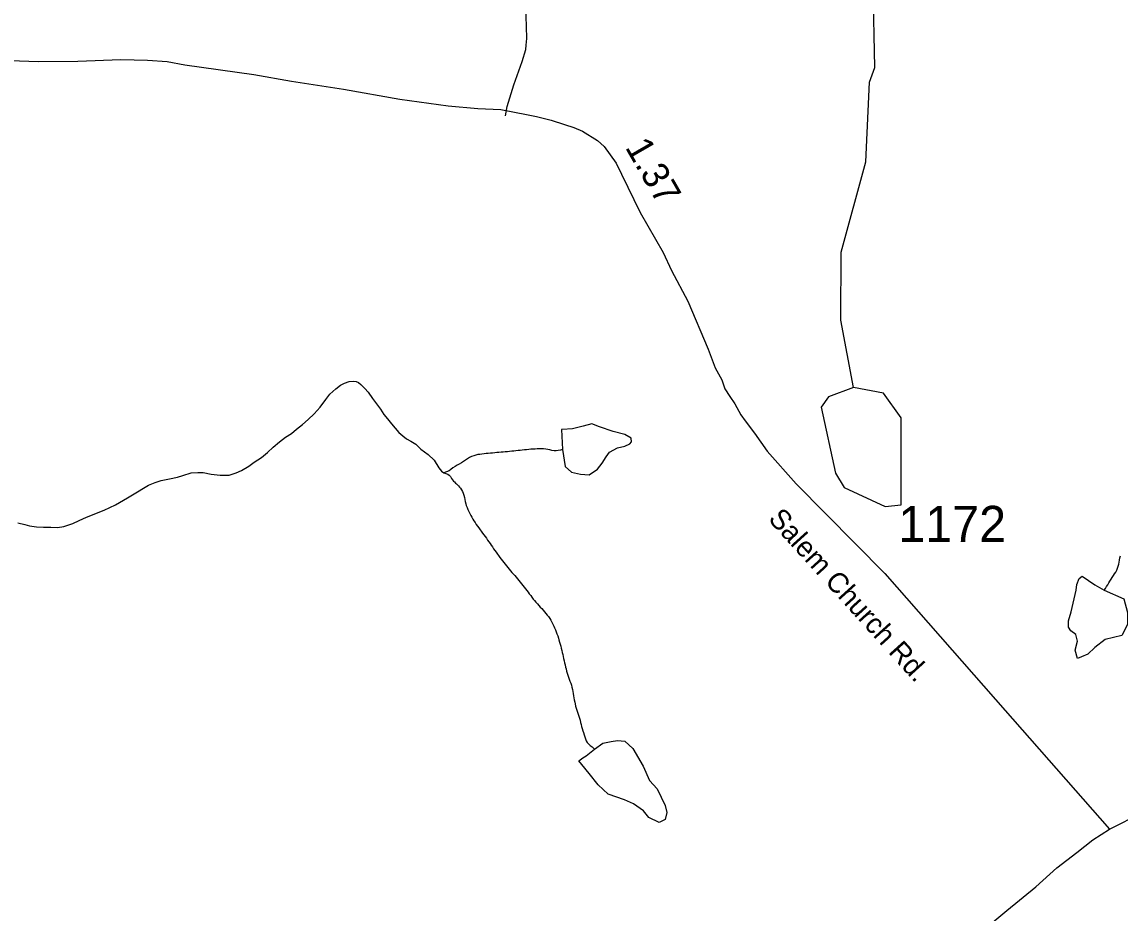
# Model space of a CAD drawing. Extents: x 1950930 to 2061844, y 904556 to 1017002.
# Drawn here: x 1961242 to 1966393, y 925393 to 929573 of the extents above; entities that cross this region are included whole.
import ezdxf

# ---------------------------------------------------------------- set-up
doc = ezdxf.new("R2010")
doc.units = 0
for name, color, linetype in [('Exist Hydrographic Creek Single Shore', 7, 'Continuous'), ('Exist Hydrographic Misc Water Feature', 7, 'Continuous'), ('Exist Road Non-System Type 51', 7, 'Continuous'), ('Exist Road Primary NC Attributed', 7, 'Continuous'), ('Exist Road Primary US Structure Standard Bridge CELL', 7, 'Continuous'), ('Exist Road Secondary Type 51 Attributed', 7, 'Continuous'), ('Exist Road Secondary Type 51 Label', 7, 'Continuous'), ('Exist Road Secondary Type 51 Number Label', 7, 'Continuous')]:
    doc.layers.add(name, color=color, linetype=linetype)

msp = doc.modelspace()

# ---------------------------------------------------------------- linework, layer by layer
at = {"layer": 'Exist Hydrographic Creek Single Shore'}
for points in [[(1965142.6, 927858.2), (1965083.6, 928174.5), (1965084.6, 928492.9), (1965200.6, 928917.2), (1965217.7, 929290.9), (1965242.7, 929359.4), (1965234.7, 929740.3), (1964918.5, 930383.4), (1964901.7, 930524.9), (1964960.5, 930691.1), (1965293.5, 930917.3), (1965435.6, 931058.8), (1965502.5, 931208.4), (1965403.6, 932175.3), (1965436.6, 932726), (1965461.7, 932758.3), (1965474.2, 932813.4), (1965470.9, 932879.2), (1965457.1, 932929.6)], [(1961222.7, 927223.6), (1961254.7, 927215.5), (1961276.6, 927209.4), (1961310.7, 927205.4), (1961342.7, 927203.3), (1961376.7, 927203.3), (1961408.7, 927201.2), (1961438.8, 927207.2), (1961480.9, 927221), (1961510.8, 927235), (1961544.8, 927251), (1961627.1, 927282.8), (1961681, 927308.7), (1961737.2, 927340.6), (1961783.1, 927368.4), (1961811.2, 927386.4), (1961835.2, 927400.4), (1961867.2, 927412.3), (1961895.3, 927422.3), (1961933.2, 927430.3), (1961971.1, 927438.2), (1961997.2, 927446.2), (1962035.3, 927458), (1962067.3, 927460), (1962091.3, 927459.9), (1962129.4, 927451.9), (1962171.3, 927447.8), (1962213.3, 927447.7), (1962247.3, 927457.6), (1962271.3, 927469.6), (1962305.4, 927489.5), (1962331.4, 927507.5), (1962365.5, 927529.4), (1962393.5, 927553.4), (1962419.6, 927579.3), (1962449.5, 927603.2), (1962477.6, 927625.2), (1962505.7, 927643.2), (1962529.7, 927663.1), (1962557.8, 927685), (1962583.8, 927709), (1962611.9, 927735), (1962640, 927767), (1962667.9, 927802.9), (1962686.2, 927826.8), (1962714, 927852.8), (1962736.2, 927868.8), (1962754.2, 927878.7), (1962776.2, 927886.6), (1962796.3, 927888.7), (1962810.2, 927886.6), (1962820.3, 927882.6), (1962832.2, 927872.6), (1962850.2, 927854.5), (1962866.2, 927836.5), (1962886.1, 927806.4), (1962900, 927788.5), (1962924, 927756.4), (1962940, 927732.3), (1962955.8, 927712.3), (1962975.9, 927688.2), (1962991.9, 927668.2), (1963009.7, 927648.2), (1963027.8, 927632.2), (1963045.8, 927618.1), (1963065.7, 927606.1), (1963089.7, 927592.1), (1963113.7, 927569.9), (1963147.5, 927543.9), (1963175.4, 927517.9), (1963197.6, 927481.8), (1963209.5, 927465.8), (1963221.3, 927457.7)], [(1963221.3, 927457.7), (1963239.4, 927451.8), (1963245.7, 927448), (1963251.5, 927440.3), (1963256.4, 927431.9), (1963261.3, 927425.8), (1963266.3, 927419.8), (1963271.4, 927415.3), (1963276.3, 927410.5), (1963281, 927405.9), (1963285.7, 927401.8), (1963290.4, 927396.7), (1963295, 927391.2), (1963299.5, 927385.6), (1963303.8, 927378.7), (1963308.1, 927370.9), (1963311.8, 927362.8), (1963314.8, 927353.9), (1963317.3, 927343), (1963319.6, 927333.2), (1963321.2, 927323.2), (1963323.7, 927313.4), (1963326.3, 927304.3), (1963330, 927295.2), (1963333.9, 927286.1), (1963338.2, 927277), (1963342.7, 927267.9), (1963347.5, 927258.7), (1963352.2, 927250.4), (1963357.3, 927241.3), (1963362.2, 927233), (1963367.5, 927224.7), (1963373.1, 927216.4), (1963378.8, 927208), (1963384.6, 927199.7), (1963390.7, 927191.4), (1963396.7, 927183.9), (1963402.4, 927175.6), (1963408.6, 927167.2), (1963414.5, 927159.7), (1963420.4, 927151.4), (1963426.2, 927143.1), (1963431.5, 927134.8), (1963437.5, 927126.5), (1963443.2, 927118.9), (1963449, 927110.6), (1963454.5, 927102.3), (1963460.4, 927094), (1963466.4, 927085.7), (1963471.9, 927077.4), (1963477.9, 927069.8), (1963483.6, 927061.5), (1963489.6, 927053.2), (1963495.7, 927045.6), (1963501.9, 927037.3), (1963508.2, 927029.8), (1963514.6, 927022.2), (1963520.9, 927014.7), (1963527.5, 927006.4), (1963533.6, 926998.8), (1963540.2, 926991.4), (1963546.8, 926983.9), (1963553.3, 926976.3), (1963559.7, 926968.8), (1963566, 926961.3), (1963572.6, 926952.9), (1963579, 926945.4), (1963585.1, 926937.9), (1963591.5, 926929.6), (1963597.2, 926922.2), (1963603.6, 926913.7), (1963609.7, 926906.3), (1963615.7, 926898), (1963621.8, 926890.5), (1963628.2, 926882.1), (1963634.1, 926874.6), (1963640.5, 926866.3), (1963646.4, 926858.8), (1963652.8, 926851.2), (1963659.5, 926843.7), (1963666.1, 926836.2), (1963672.9, 926828.6), (1963679.8, 926821.2), (1963686.4, 926813.7), (1963693.6, 926806.1), (1963699.9, 926798.6), (1963706.3, 926791.1), (1963712.4, 926783.5), (1963718, 926775.2), (1963722.9, 926766.9), (1963727.6, 926757.8), (1963732.1, 926748.7), (1963736.4, 926739.6), (1963740.3, 926730.4), (1963744.4, 926721.3), (1963747.9, 926712.3), (1963751.4, 926702.3), (1963754.9, 926693.2), (1963758, 926683.4), (1963761, 926674.2)], [(1966319.3, 926907.8), (1966324.6, 926915.9), (1966330.1, 926924.8), (1966335.5, 926932.9), (1966340.8, 926941.8), (1966345.9, 926949.9), (1966351.5, 926958.9), (1966356.6, 926967), (1966361.9, 926975.9), (1966367.5, 926984), (1966372.8, 926992.9), (1966377.3, 927001), (1966381.2, 927010.7), (1966384.5, 927019.7), (1966386.7, 927029.5), (1966388.6, 927039.3), (1966390.4, 927049.1), (1966392.5, 927058.9), (1966394.7, 927068.7)], [(1963761, 926674.2), (1963764.1, 926664.3), (1963766.8, 926654.5), (1963769.4, 926645.3), (1963771.9, 926635.5), (1963774.2, 926625.5), (1963776.4, 926615.6), (1963778.7, 926606.6), (1963780.9, 926596.7), (1963783, 926586.8), (1963785, 926576.9), (1963787.3, 926567), (1963789.3, 926557.2), (1963791.6, 926547.2), (1963794.1, 926538.2), (1963796.5, 926528.2), (1963799.2, 926518.4), (1963802.3, 926509.3), (1963805.5, 926499.3), (1963809.2, 926490.2), (1963812.7, 926480.4), (1963816.2, 926471.2), (1963819.1, 926462.2), (1963821.5, 926452.3), (1963823.8, 926442.3), (1963826, 926432.5), (1963827.7, 926422.6), (1963829.5, 926412.7), (1963831.2, 926402.9), (1963833, 926392.9), (1963834.7, 926383.1), (1963836.9, 926374), (1963839.2, 926364.1), (1963841.6, 926354.3), (1963844.7, 926345.1), (1963847.8, 926335.3), (1963851.5, 926326.2), (1963854.5, 926316.2), (1963857.4, 926307.1), (1963860.1, 926297.3), (1963862.3, 926287.3), (1963864.8, 926277.5), (1963867.3, 926268.3), (1963869.9, 926258.4), (1963872.8, 926248.6), (1963875.7, 926239.5), (1963878.5, 926229.6), (1963881.6, 926219.6), (1963885.1, 926210.5), (1963889.2, 926201.4), (1963893.9, 926193.1), (1963900.5, 926185.6), (1963907.9, 926178.9), (1963916.1, 926172.2), (1963928, 926162)]]:
    msp.add_lwpolyline(points, dxfattribs=at)
at = {"layer": 'Exist Hydrographic Misc Water Feature'}
for points in [[(1965142.6, 927858.2), (1965025.5, 927814.8), (1964991.5, 927766.2), (1965058.5, 927456.3), (1965099.6, 927389.8), (1965291.7, 927300.6), (1965366.5, 927308.8), (1965366.5, 927715.7), (1965283.7, 927832.4), (1965142.6, 927858.2)], [(1963777.4, 927567.5), (1963790.2, 927487.6), (1963820.1, 927461.4), (1963862.1, 927451.6), (1963902.3, 927448.3), (1963942.1, 927476.2), (1963963.8, 927502.9), (1963981.7, 927532.9), (1963997.5, 927554.6), (1964035.2, 927575.2), (1964069.2, 927583.5), (1964093, 927593.7), (1964101, 927603.4), (1964099, 927621.5), (1964070.7, 927637.7), (1964014.7, 927652.8), (1963950.5, 927674.6), (1963914.4, 927688.4), (1963874.4, 927677.8), (1963824.8, 927664), (1963776.6, 927661), (1963772.5, 927661.1), (1963777.4, 927567.5)], [(1963777.4, 927567.5), (1963767.4, 927565.2), (1963757.8, 927562.8), (1963747.9, 927561.4), (1963738.1, 927561.7), (1963728.2, 927563.5), (1963718.2, 927566.1), (1963708.5, 927568), (1963698.7, 927569.8), (1963688.9, 927570.8), (1963678.8, 927571.1), (1963668.8, 927571.2), (1963658.7, 927570.6), (1963648.9, 927570), (1963638.8, 927569.4), (1963628.8, 927568.9), (1963618.9, 927568.3), (1963609.1, 927566.7), (1963598.8, 927566.1), (1963589, 927564.7), (1963579, 927563.2), (1963569.1, 927562.6), (1963559.3, 927561.2), (1963549.4, 927559.8), (1963539.2, 927559.1), (1963529.3, 927558.5), (1963519.3, 927557.2), (1963509.2, 927556.5), (1963499.4, 927555.9), (1963489.6, 927555.3), (1963479.5, 927553.8), (1963469.5, 927553.2), (1963459.4, 927552.6), (1963449.6, 927551.2), (1963439.5, 927550.6), (1963429.5, 927549.2), (1963419.8, 927548.5), (1963409.8, 927547.9), (1963399.7, 927546.4), (1963389.9, 927545), (1963380.1, 927543.6), (1963370.4, 927541.3), (1963360.8, 927538.2), (1963351.3, 927535.2), (1963341.7, 927530.2), (1963332.3, 927523.7), (1963322.8, 927517.3), (1963313.2, 927511), (1963303.2, 927505.2), (1963293.3, 927499.5), (1963283.1, 927493.8), (1963273.4, 927487.6), (1963263.6, 927481.6), (1963254.4, 927474.4), (1963245.3, 927468.3), (1963221.3, 927457.7)], [(1966319.3, 926907.8), (1966411.5, 926866.6), (1966428.2, 926803), (1966428.6, 926746.4), (1966400.9, 926694.4), (1966323.2, 926675.6), (1966275.4, 926639.6), (1966241.8, 926607.5), (1966211.8, 926595), (1966193.8, 926587.1), (1966183.3, 926626.8), (1966193.2, 926669.2), (1966185, 926700.6), (1966162.8, 926716.6), (1966150.7, 926734.8), (1966150.7, 926764.5), (1966164, 926806.8), (1966173.9, 926846.8), (1966187.4, 926907.3), (1966191.1, 926935.1), (1966201, 926962.8), (1966214.7, 926973.1), (1966275.2, 926933.3), (1966319.3, 926907.8)], [(1963928, 926162), (1963966.1, 926190), (1964005.7, 926198.2), (1964035.8, 926202.5), (1964069.8, 926199.3), (1964108, 926164.9), (1964156.6, 926081.9), (1964185.1, 926015.7), (1964221.6, 925976.4), (1964259.9, 925898.4), (1964266.3, 925864.7), (1964258.5, 925832), (1964230.6, 925817.8), (1964182.4, 925841.8), (1964158.2, 925873.4), (1964110, 925905.6), (1964068, 925924.6), (1963991.7, 925950.7), (1963945.2, 925994.4), (1963902.9, 926047.7), (1963868.7, 926089.5), (1963854.5, 926107), (1963872.4, 926121.3), (1963888.4, 926130), (1963928, 926162)]]:
    msp.add_lwpolyline(points, dxfattribs=at)
at = {"layer": 'Exist Road Non-System Type 51'}
msp.add_lwpolyline([(1963509.8, 929132.3), (1963517.5, 929176.1), (1963549.1, 929277.9), (1963587.9, 929388.2), (1963604.9, 929444.1), (1963607.2, 929464.6), (1963610.9, 929496.2), (1963608.5, 929551.9), (1963604.9, 929646.5), (1963603.6, 929905.4), (1963613.4, 930002.9), (1963612.1, 930034.5), (1963601.2, 930146), (1963595.1, 930195.8), (1963597.6, 930220), (1963604.9, 930255.1)], dxfattribs=at)
at = {"layer": 'Exist Road Primary NC Attributed'}
for points in [[(1966343.6, 925786.3), (1966499.2, 925864.6)], [(1965587.5, 925175.4), (1965861.5, 925405.7), (1965998.2, 925516.6), (1966096.1, 925605.5), (1966190.2, 925676.9), (1966266.1, 925736.2), (1966343.6, 925786.3)]]:
    msp.add_lwpolyline(points, dxfattribs=at)
at = {"layer": 'Exist Road Secondary Type 51 Attributed'}
msp.add_lwpolyline([(1961187, 929391.9), (1961318.2, 929388.5), (1961503.1, 929390), (1961705.1, 929396.8), (1961831.1, 929394), (1961923.2, 929387.3), (1962005.1, 929372.9), (1962328.9, 929327), (1962506.7, 929295.9), (1962750.4, 929258.5), (1963014.3, 929210.8), (1963241.5, 929180.3), (1963380, 929166.8), (1963487.8, 929162.2), (1963560.6, 929148.5), (1963601.6, 929140.9), (1963656.3, 929130.3), (1963724.6, 929112), (1963786.9, 929092.3), (1963830.9, 929078.6), (1963871.9, 929060.4), (1963941.7, 929017.8), (1963973.6, 928988.9), (1964029, 928910.7), (1964054.8, 928859), (1964141.2, 928679.6), (1964249.4, 928491.7), (1964289.5, 928407.7), (1964365.7, 928263.9), (1964460.1, 928038.1), (1964494.3, 927950.1), (1964524.4, 927894.1), (1964538.4, 927852.1), (1964562.5, 927816.1), (1964586.5, 927782.3), (1964614.8, 927730.4), (1964634.8, 927702.3), (1964678.8, 927644.3), (1964736.9, 927560.5), (1964873.1, 927406.7), (1965289.2, 926985.4), (1965808.6, 926394.2), (1966343.6, 925786.3)], dxfattribs=at)

# ---------------------------------------------------------------- texts
at = {"layer": 'Exist Road Primary US Structure Standard Bridge CELL'}
msp.add_text('1.37', height=125, rotation=299.9436, dxfattribs=at).set_placement((1964069.1, 928985.5))
at = {"layer": 'Exist Road Secondary Type 51 Label'}
msp.add_text('Salem Church Rd.', height=95, rotation=312.1446, dxfattribs=at).set_placement((1964738.7, 927239))
at = {"layer": 'Exist Road Secondary Type 51 Number Label'}
msp.add_text('1172', height=170, dxfattribs=at).set_placement((1965352.7, 927133.3))

doc.saveas('drawing.dxf')
